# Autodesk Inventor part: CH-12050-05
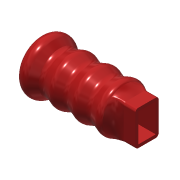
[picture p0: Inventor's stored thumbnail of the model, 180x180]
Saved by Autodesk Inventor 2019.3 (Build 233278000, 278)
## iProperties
Created: 2012-07
Part Number: CH-12050-05
Material: Ogólny
Document SubType Name: Modeling
Designer: CADENGINEERING4
Density: 1 g/cm^3
Appearance: Jasnoczerwona
Author: CADENGINEERING4
Revision Number: ÈÎºÎ
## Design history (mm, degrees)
feature "ÇÐ³ý-À­Éì1"
node "Bryła1"
